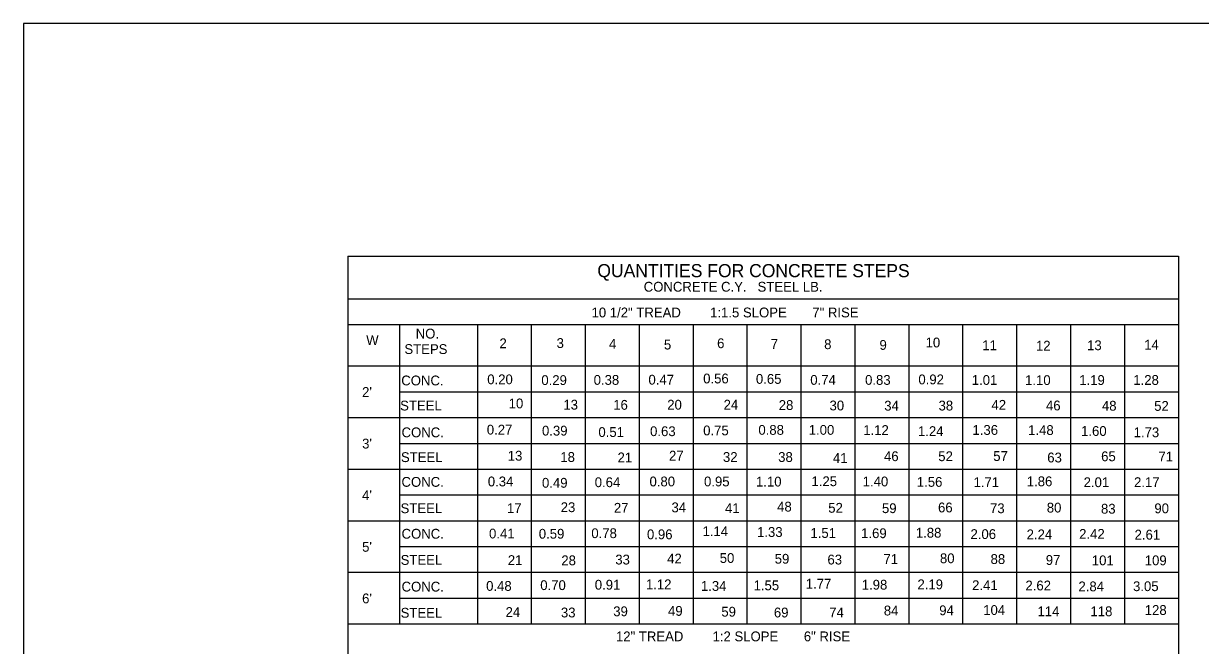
# Model space of a CAD drawing. Extents: x -439.5 to -408.2, y -792 to -771.6.
# Drawn here: x -439.46 to -422.81, y -780.41 to -771.61 of the extents above; entities that cross this region are included whole.
import ezdxf

# ---------------------------------------------------------------- set-up
doc = ezdxf.new("R2010")
doc.units = 0
doc.layers.add('Bridge-Named Boundary', color=7, linetype='Continuous')
doc.layers.add('Level 4', color=7, linetype='Continuous')

msp = doc.modelspace()

# ---------------------------------------------------------------- linework, layer by layer
at = {"layer": 'Bridge-Named Boundary'}
msp.add_lwpolyline([(-439.459, -791.984), (-408.209, -791.984), (-408.209, -771.609), (-439.459, -771.609)], close=True, dxfattribs=at)
at = {"layer": 'Level 4'}
for p, q in [((-434.87, -774.903), (-434.87, -789.286)), ((-434.87, -774.903), (-423.125, -774.903)), ((-423.125, -774.903), (-423.125, -789.286)), ((-434.87, -775.505), (-423.125, -775.505)), ((-434.87, -775.868), (-423.125, -775.868)), ((-434.143, -775.868), (-434.143, -780.105)), ((-433.04, -775.868), (-433.04, -780.105)), ((-432.278, -775.868), (-432.278, -780.105)), ((-431.515, -775.868), (-431.515, -780.105)), ((-430.753, -775.868), (-430.753, -780.105)), ((-429.989, -775.868), (-429.989, -780.105)), ((-429.227, -775.868), (-429.227, -780.105)), ((-428.464, -775.868), (-428.464, -780.105)), ((-427.702, -775.868), (-427.702, -780.105)), ((-426.938, -775.868), (-426.938, -780.105)), ((-426.176, -775.868), (-426.176, -780.105)), ((-425.412, -775.868), (-425.412, -780.105)), ((-424.65, -775.868), (-424.65, -780.105)), ((-423.887, -775.868), (-423.887, -780.105)), ((-434.87, -776.453), (-423.125, -776.453)), ((-434.143, -776.818), (-423.125, -776.818)), ((-434.87, -777.184), (-423.125, -777.184)), ((-434.143, -777.549), (-423.125, -777.549)), ((-434.87, -777.914), (-423.125, -777.914)), ((-434.143, -778.279), (-423.125, -778.279)), ((-434.87, -778.645), (-423.125, -778.645)), ((-434.143, -779.01), (-423.125, -779.01)), ((-434.87, -779.374), (-423.125, -779.374)), ((-434.143, -779.74), (-423.125, -779.74)), ((-434.87, -780.105), (-423.125, -780.105))]:
    msp.add_line(p, q, dxfattribs=at)
msp.add_ellipse((-431.616, -777.094), major_axis=(0.099, 0), ratio=0.96313, start_param=1.96543, end_param=2.160216, dxfattribs=at)

# ---------------------------------------------------------------- texts
for s, height, p in [('QUANTITIES FOR CONCRETE STEPS', 0.18523, (-431.343, -775.198)), ('CONCRETE C.Y.   STEEL LB.', 0.13893, (-430.687, -775.403)), ('10 1/2" TREAD        1:1.5 SLOPE       7" RISE', 0.13893, (-431.425, -775.767)), ('W', 0.139, (-434.612, -776.159)), ('NO.', 0.1389, (-433.912, -776.066)), ('3', 0.139, (-431.919, -776.2)), ('6', 0.139, (-429.649, -776.202)), ('10', 0.1389, (-426.7, -776.192)), ('STEPS', 0.1389, (-434.072, -776.285)), ('2', 0.139, (-432.727, -776.203)), ('4', 0.139, (-431.178, -776.211)), ('5', 0.139, (-430.401, -776.221)), ('7', 0.139, (-428.89, -776.212)), ('8', 0.139, (-428.135, -776.216)), ('9', 0.139, (-427.352, -776.226)), ('11', 0.1389, (-425.899, -776.231)), ('12', 0.1389, (-425.139, -776.237)), ('13', 0.1389, (-424.416, -776.231)), ('14', 0.1389, (-423.608, -776.223)), ('0.56', 0.1389, (-429.846, -776.701)), ('CONC.', 0.1389, (-434.116, -776.729)), ('0.20', 0.1389, (-432.9, -776.713)), ('0.29', 0.1389, (-432.135, -776.724)), ('0.38', 0.1389, (-431.395, -776.721)), ('0.47', 0.1389, (-430.62, -776.718)), ('0.65', 0.1389, (-429.1, -776.707)), ('0.74', 0.1389, (-428.331, -776.721)), ('0.83', 0.1389, (-427.556, -776.721)), ('0.92', 0.1389, (-426.802, -776.714)), ('1.01', 0.1389, (-426.047, -776.722)), ('1.10', 0.1389, (-425.293, -776.724)), ('1.19', 0.1389, (-424.527, -776.723)), ('1.28', 0.1389, (-423.762, -776.722)), ("2'", 0.1389, (-434.67, -776.892)), ('STEEL', 0.1389, (-434.132, -777.084)), ('10', 0.1389, (-432.597, -777.054)), ('13', 0.1389, (-431.823, -777.072)), ('16', 0.1389, (-431.118, -777.074)), ('20', 0.1389, (-430.354, -777.072)), ('24', 0.1389, (-429.557, -777.072)), ('28', 0.1389, (-428.777, -777.077)), ('30', 0.1389, (-428.059, -777.083)), ('34', 0.1389, (-427.285, -777.086)), ('38', 0.1389, (-426.517, -777.084)), ('42', 0.1389, (-425.768, -777.074)), ('46', 0.1389, (-424.997, -777.083)), ('48', 0.1389, (-424.206, -777.087)), ('52', 0.1389, (-423.467, -777.089)), ('CONC.', 0.1389, (-434.112, -777.463)), ('0.27', 0.1389, (-432.906, -777.425)), ('0.39', 0.1389, (-432.126, -777.439)), ('0.51', 0.1389, (-431.328, -777.459)), ('0.63', 0.1389, (-430.597, -777.447)), ('0.75', 0.1389, (-429.846, -777.436)), ('0.88', 0.1389, (-429.065, -777.428)), ('1.00', 0.1389, (-428.353, -777.428)), ('1.12', 0.1389, (-427.582, -777.431)), ('1.24', 0.1389, (-426.808, -777.446)), ('1.36', 0.1389, (-426.037, -777.429)), ('1.48', 0.1389, (-425.25, -777.431)), ('1.60', 0.1389, (-424.501, -777.444)), ('1.73', 0.1389, (-423.757, -777.462)), ("3'", 0.1389, (-434.67, -777.622)), ('STEEL', 0.1389, (-434.121, -777.814)), ('13', 0.1389, (-432.61, -777.794)), ('18', 0.1389, (-431.866, -777.812)), ('21', 0.1389, (-431.057, -777.818)), ('27', 0.1389, (-430.329, -777.793)), ('32', 0.1389, (-429.566, -777.812)), ('38', 0.1389, (-428.785, -777.812)), ('41', 0.1389, (-428.011, -777.826)), ('46', 0.1389, (-427.288, -777.801)), ('52', 0.1389, (-426.521, -777.801)), ('57', 0.1389, (-425.743, -777.798)), ('63', 0.1389, (-424.979, -777.819)), ('65', 0.1389, (-424.217, -777.802)), ('71', 0.1389, (-423.406, -777.805)), ('CONC.', 0.1389, (-434.113, -778.164)), ('0.34', 0.1389, (-432.892, -778.158)), ('0.49', 0.1389, (-432.126, -778.177)), ('0.64', 0.1389, (-431.38, -778.169)), ('0.80', 0.1389, (-430.605, -778.158)), ('0.95', 0.1389, (-429.834, -778.158)), ('1.10', 0.1389, (-429.099, -778.16)), ('1.25', 0.1389, (-428.314, -778.155)), ('1.40', 0.1389, (-427.59, -778.158)), ('1.56', 0.1389, (-426.824, -778.164)), ('1.71', 0.1389, (-426.022, -778.168)), ('1.86', 0.1389, (-425.269, -778.156)), ('2.01', 0.1389, (-424.465, -778.169)), ('2.17', 0.1389, (-423.752, -778.168)), ("4'", 0.1389, (-434.67, -778.352)), ('23', 0.1389, (-431.861, -778.522)), ('27', 0.1389, (-431.109, -778.531)), ('34', 0.1389, (-430.294, -778.525)), ('48', 0.1389, (-428.8, -778.514)), ('52', 0.1389, (-428.077, -778.531)), ('66', 0.1389, (-426.524, -778.526)), ('80', 0.1389, (-424.986, -778.528)), ('STEEL', 0.1389, (-434.126, -778.537)), ('17', 0.1389, (-432.621, -778.536)), ('41', 0.1389, (-429.537, -778.536)), ('59', 0.1389, (-427.317, -778.536)), ('73', 0.1389, (-425.789, -778.537)), ('83', 0.1389, (-424.219, -778.544)), ('90', 0.1389, (-423.464, -778.538)), ('1.14', 0.1389, (-429.855, -778.862)), ('CONC.', 0.1389, (-434.112, -778.898)), ('0.41', 0.1389, (-432.875, -778.895)), ('0.59', 0.1389, (-432.171, -778.898)), ('0.78', 0.1389, (-431.428, -778.89)), ('0.96', 0.1389, (-430.641, -778.906)), ('1.33', 0.1389, (-429.084, -778.873)), ('1.51', 0.1389, (-428.329, -778.887)), ('1.69', 0.1389, (-427.612, -778.89)), ('1.88', 0.1389, (-426.838, -778.883)), ('2.06', 0.1389, (-426.065, -778.903)), ('2.24', 0.1389, (-425.271, -778.907)), ('2.42', 0.1389, (-424.528, -778.9)), ('2.61', 0.1389, (-423.744, -778.911)), ("5'", 0.1389, (-434.67, -779.083)), ('STEEL', 0.1389, (-434.125, -779.268)), ('21', 0.1389, (-432.609, -779.271)), ('28', 0.1389, (-431.852, -779.274)), ('33', 0.1389, (-431.089, -779.263)), ('42', 0.1389, (-430.355, -779.249)), ('50', 0.1389, (-429.612, -779.241)), ('59', 0.1389, (-428.834, -779.252)), ('63', 0.1389, (-428.088, -779.263)), ('71', 0.1389, (-427.296, -779.255)), ('80', 0.1389, (-426.497, -779.245)), ('88', 0.1389, (-425.781, -779.256)), ('97', 0.1389, (-425, -779.269)), ('101', 0.1389, (-424.349, -779.274)), ('109', 0.1389, (-423.6, -779.274)), ('CONC.', 0.1389, (-434.112, -779.646)), ('0.48', 0.1389, (-432.916, -779.636)), ('0.70', 0.1389, (-432.15, -779.625)), ('0.91', 0.1389, (-431.379, -779.619)), ('1.12', 0.1389, (-430.656, -779.614)), ('1.34', 0.1389, (-429.878, -779.636)), ('1.55', 0.1389, (-429.133, -779.628)), ('1.77', 0.1389, (-428.395, -779.605)), ('1.98', 0.1389, (-427.603, -779.619)), ('2.19', 0.1389, (-426.815, -779.614)), ('2.41', 0.1389, (-426.042, -779.626)), ('2.62', 0.1389, (-425.288, -779.63)), ('2.84', 0.1389, (-424.538, -779.643)), ('3.05', 0.1389, (-423.766, -779.64)), ("6'", 0.1389, (-434.67, -779.813)), ('STEEL', 0.1389, (-434.125, -780.016)), ('24', 0.1389, (-432.641, -780.006)), ('33', 0.1389, (-431.858, -780.012)), ('39', 0.1389, (-431.118, -779.995)), ('49', 0.1389, (-430.343, -779.989)), ('59', 0.1389, (-429.589, -780.001)), ('69', 0.1389, (-428.846, -780.012)), ('74', 0.1389, (-428.063, -780.011)), ('84', 0.1389, (-427.291, -779.984)), ('94', 0.1389, (-426.507, -779.981)), ('104', 0.1389, (-425.885, -779.977)), ('114', 0.1389, (-425.117, -779.995)), ('118', 0.1389, (-424.368, -779.995)), ('128', 0.1389, (-423.6, -779.977)), ('12" TREAD        1:2 SLOPE       6" RISE', 0.13893, (-431.08, -780.35))]:
    msp.add_text(s, height=height, dxfattribs=at).set_placement(p)

doc.saveas('drawing.dxf')
